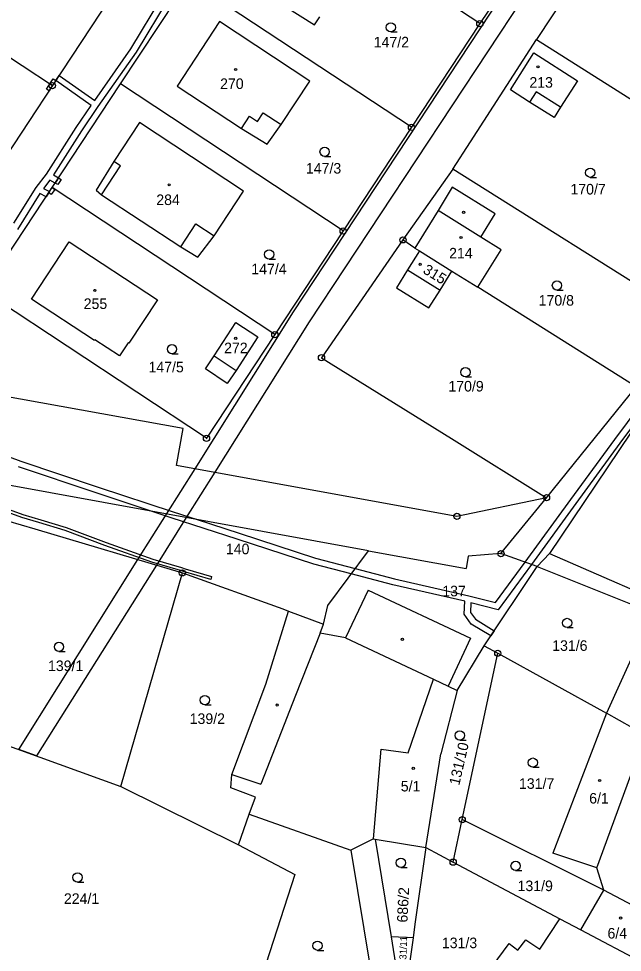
# Model space of a CAD drawing. Extents: x -747333 to -745433, y -1133152 to -1130600.
# Drawn here: x -746539.4 to -746442.1, y -1132011.9 to -1131861.6 of the extents above; entities that cross this region are included whole.
import ezdxf

# ---------------------------------------------------------------- set-up
doc = ezdxf.new("R2010")
doc.units = 0
for name, color, linetype in [('Vrstva 1', 7, 'Continuous'), ('Vrstva 18', 7, 'Continuous'), ('Vrstva 19', 7, 'Continuous'), ('Vrstva 24', 7, 'Continuous'), ('Vrstva 25', 7, 'Continuous'), ('Vrstva 3', 7, 'Continuous'), ('Vrstva 30', 7, 'Continuous'), ('Vrstva 37', 7, 'Continuous'), ('Vrstva 4', 7, 'Continuous'), ('Vrstva 6', 7, 'Continuous')]:
    doc.layers.add(name, color=color, linetype=linetype)

msp = doc.modelspace()

# ---------------------------------------------------------------- linework, layer by layer
at = {"layer": 'Vrstva 1'}
for p, q in [((-746465.11, -1131862.35), (-746501.01, -1131838.68)), ((-746454.1, -1131845.66), (-746465.11, -1131862.35)), ((-746523.03, -1131872.07), (-746512.02, -1131855.37)), ((-746476.13, -1131879.05), (-746512.02, -1131855.37)), ((-746496.38, -1131859.65), (-746491.75, -1131862.56)), ((-746491.75, -1131862.56), (-746490.9, -1131861.24)), ((-746507.05, -1131862.03), (-746513.9, -1131872.45)), ((-746492.5, -1131871.6), (-746507.05, -1131862.03)), ((-746465.11, -1131862.35), (-746476.13, -1131879.05)), ((-746534.04, -1131888.76), (-746523.03, -1131872.07)), ((-746487.14, -1131895.74), (-746523.03, -1131872.07)), ((-746513.9, -1131872.45), (-746503.53, -1131879.26)), ((-746497.13, -1131878.62), (-746492.5, -1131871.6)), ((-746519.95, -1131878.28), (-746524.08, -1131884.54)), ((-746503.2, -1131889.33), (-746519.95, -1131878.28)), ((-746503.53, -1131879.26), (-746499.39, -1131881.78)), ((-746499.39, -1131881.78), (-746497.13, -1131878.62)), ((-746476.13, -1131879.05), (-746487.14, -1131895.74)), ((-746524.08, -1131884.54), (-746526.95, -1131889.18)), ((-746545.06, -1131905.46), (-746534.04, -1131888.76)), ((-746498.15, -1131912.44), (-746534.04, -1131888.76)), ((-746526.95, -1131889.18), (-746526.08, -1131889.91)), ((-746526.08, -1131889.91), (-746513.32, -1131898.32)), ((-746507.95, -1131896.52), (-746503.2, -1131889.33)), ((-746510.54, -1131899.99), (-746507.95, -1131896.52)), ((-746487.14, -1131895.74), (-746498.15, -1131912.44)), ((-746513.32, -1131898.32), (-746510.54, -1131899.99)), ((-746474.85, -1131898.97), (-746476.75, -1131902)), ((-746475.58, -1131898.52), (-746474.85, -1131898.97)), ((-746474.85, -1131898.97), (-746469.61, -1131902.21)), ((-746476.75, -1131902), (-746478.56, -1131904.89)), ((-746471.53, -1131905.27), (-746469.61, -1131902.21)), ((-746469.61, -1131902.21), (-746465.42, -1131904.8)), ((-746509.16, -1131929.13), (-746545.06, -1131905.46)), ((-746478.56, -1131904.89), (-746473.31, -1131908.12)), ((-746473.31, -1131908.12), (-746471.53, -1131905.27)), ((-746507.95, -1131915.87), (-746504.45, -1131910.49)), ((-746504.45, -1131910.49), (-746500.88, -1131912.81)), ((-746498.15, -1131912.44), (-746509.16, -1131929.13)), ((-746500.88, -1131912.81), (-746504.4, -1131918.2)), ((-746509.31, -1131917.93), (-746507.95, -1131915.87)), ((-746505.85, -1131920.3), (-746509.31, -1131917.93)), ((-746504.4, -1131918.2), (-746505.85, -1131920.3)), ((-746512.94, -1131927.58), (-746542.46, -1131922.22)), ((-746514.01, -1131933.49), (-746512.94, -1131927.58)), ((-746483.07, -1131947.25), (-746560.7, -1131933.13)), ((-746468.81, -1131941.71), (-746514.01, -1131933.49)), ((-746454.36, -1131938.7), (-746468.81, -1131941.71)), ((-746489.62, -1131956.07), (-746483.07, -1131947.25)), ((-746483.07, -1131947.25), (-746467.34, -1131950.11)), ((-746461.71, -1131947.7), (-746466.99, -1131948.14)), ((-746466.99, -1131948.14), (-746467.34, -1131950.11))]:
    msp.add_line(p, q, dxfattribs=at)
for points in [[(-746443.47, -1131845.95), (-746455.99, -1131864.91)], [(-746521.6, -1131853.55), (-746533.99, -1131872.33)], [(-746466.63, -1131881.37), (-746455.99, -1131864.91)], [(-746455.99, -1131864.91), (-746418.01, -1131888.89)], [(-746543.81, -1131865.86), (-746533.99, -1131872.33)], [(-746460.17, -1131873.04), (-746456.41, -1131867.08)], [(-746456.41, -1131867.08), (-746449.39, -1131871.54)], [(-746533.99, -1131872.33), (-746537.79, -1131878.09)], [(-746449.39, -1131871.54), (-746452.09, -1131875.82)], [(-746457.09, -1131875.01), (-746460.17, -1131873.04)], [(-746453.14, -1131877.48), (-746457.09, -1131875.01)], [(-746452.09, -1131875.82), (-746453.14, -1131877.48)], [(-746537.79, -1131878.09), (-746546.37, -1131891.11)], [(-746469.48, -1131885.78), (-746466.63, -1131881.37)], [(-746469.48, -1131885.78), (-746477.5, -1131897.18)], [(-746431.68, -1131909.51), (-746469.48, -1131885.78)], [(-746469.56, -1131888.71), (-746471.81, -1131892.44)], [(-746462.62, -1131892.99), (-746469.56, -1131888.71)], [(-746471.81, -1131892.44), (-746475.58, -1131898.52)], [(-746464.95, -1131896.72), (-746462.62, -1131892.99)], [(-746537.36, -1131906.73), (-746531.27, -1131897.47), (-746517.04, -1131906.83), (-746521.67, -1131913.82), (-746521.78, -1131913.76), (-746523.18, -1131915.87), (-746527.14, -1131913.27), (-746527.21, -1131913.37), (-746537.36, -1131906.73)], [(-746477.5, -1131897.18), (-746490.63, -1131916.16)], [(-746475.58, -1131898.52), (-746477.5, -1131897.18)], [(-746461.69, -1131898.76), (-746464.95, -1131896.72)], [(-746465.42, -1131904.8), (-746461.69, -1131898.76)], [(-746439.92, -1131920.87), (-746465.42, -1131904.8)], [(-746490.63, -1131916.16), (-746469.66, -1131929.19)], [(-746454.36, -1131938.7), (-746439.92, -1131920.87)], [(-746438.95, -1131925.52), (-746453.89, -1131947.67)], [(-746469.66, -1131929.19), (-746454.36, -1131938.7)], [(-746461.71, -1131947.7), (-746454.36, -1131938.7)], [(-746543.47, -1131941.76), (-746536.83, -1131943.73)], [(-746536.83, -1131943.73), (-746513.04, -1131950.81)], [(-746455.89, -1131949.78), (-746461.71, -1131947.7)], [(-746455.89, -1131949.78), (-746453.89, -1131947.67)], [(-746453.89, -1131947.67), (-746430.93, -1131957.68)], [(-746464.41, -1131962.54), (-746455.89, -1131949.78)], [(-746455.89, -1131949.78), (-746437.32, -1131957.2)], [(-746522.94, -1131985.19), (-746513.04, -1131950.81)], [(-746513.04, -1131950.81), (-746496.86, -1131956.6)], [(-746483.11, -1131953.58), (-746486.74, -1131961.29)], [(-746483.11, -1131953.58), (-746466.6, -1131961.34)], [(-746496.86, -1131956.6), (-746495.93, -1131956.95)], [(-746499.59, -1131968.72), (-746495.93, -1131956.95)], [(-746495.93, -1131956.95), (-746490.28, -1131959.09)], [(-746437.32, -1131957.2), (-746444.69, -1131973.38)], [(-746490.84, -1131960.52), (-746490.28, -1131959.09)], [(-746486.74, -1131961.29), (-746490.84, -1131960.52)], [(-746466.6, -1131961.34), (-746470.23, -1131969.05)], [(-746468.74, -1131969.75), (-746464.41, -1131962.54)], [(-746464.41, -1131962.54), (-746462.22, -1131963.75)], [(-746467.95, -1131990.55), (-746462.22, -1131963.75)], [(-746462.22, -1131963.75), (-746444.69, -1131973.38)], [(-746505.1, -1131983.28), (-746499.59, -1131968.72)], [(-746468.74, -1131969.75), (-746471.42, -1131979.96)], [(-746470.23, -1131969.05), (-746468.74, -1131969.75)], [(-746552.82, -1131974.44), (-746522.94, -1131985.19)], [(-746444.69, -1131973.38), (-746453.36, -1131995.97)], [(-746438.41, -1131976.96), (-746444.69, -1131973.38)], [(-746473.83, -1131995.06), (-746471.42, -1131979.96)], [(-746505.25, -1131985.42), (-746505.1, -1131983.28)], [(-746522.94, -1131985.19), (-746504, -1131994.6)], [(-746501.26, -1131986.91), (-746505.25, -1131985.42)], [(-746502.27, -1131989.69), (-746501.26, -1131986.91)], [(-746504, -1131994.6), (-746502.27, -1131989.69)], [(-746502.27, -1131989.69), (-746485.89, -1131995.45)], [(-746469.41, -1131997.4), (-746467.95, -1131990.55)], [(-746445.14, -1132001.9), (-746467.95, -1131990.55)], [(-746482.26, -1131993.62), (-746485.89, -1131995.45)], [(-746482.26, -1131993.62), (-746481.99, -1131993.67)], [(-746481.99, -1131993.67), (-746473.83, -1131995.06)], [(-746481.99, -1131993.67), (-746479.42, -1132009.41)], [(-746504, -1131994.6), (-746494.93, -1131999.39)], [(-746485.89, -1131995.45), (-746480.65, -1132027.32)], [(-746473.83, -1131995.06), (-746475.57, -1132007.36)], [(-746473.83, -1131995.06), (-746469.41, -1131997.4)], [(-746446.26, -1131998.3), (-746453.36, -1131995.97)], [(-746469.41, -1131997.4), (-746452.2, -1132006.5)], [(-746445.14, -1132001.9), (-746446.26, -1131998.3)], [(-746494.93, -1131999.39), (-746499.57, -1132013.64)], [(-746448.81, -1132008.32), (-746445.14, -1132001.9)], [(-746434.75, -1132007.36), (-746445.14, -1132001.9)], [(-746475.57, -1132007.36), (-746475.88, -1132009.57)], [(-746455.47, -1132011.39), (-746452.2, -1132006.5)], [(-746452.2, -1132006.5), (-746448.81, -1132008.32)], [(-746448.81, -1132008.32), (-746438.69, -1132013.68)], [(-746479.42, -1132009.41), (-746477.54, -1132021.27)], [(-746475.88, -1132009.57), (-746479.42, -1132009.41)], [(-746475.88, -1132009.57), (-746477.54, -1132021.27)], [(-746463.13, -1132014.2), (-746460.4, -1132010.51)], [(-746460.4, -1132010.51), (-746459.01, -1132011.55)], [(-746459.01, -1132011.55), (-746457.7, -1132009.89)], [(-746457.7, -1132009.89), (-746455.47, -1132011.39)]]:
    msp.add_lwpolyline(points, dxfattribs=at)
at = {"layer": 'Vrstva 24'}
for p, q in [((-746465.145355, -1131862.314645), (-746465.074645, -1131862.385355)), ((-746534.04, -1131872.33), (-746533.94, -1131872.33)), ((-746476.165355, -1131879.014645), (-746476.094645, -1131879.085355)), ((-746487.175355, -1131895.704645), (-746487.104645, -1131895.775355)), ((-746477.55, -1131897.18), (-746477.45, -1131897.18)), ((-746498.185355, -1131912.404645), (-746498.114645, -1131912.475355)), ((-746490.68, -1131916.16), (-746490.58, -1131916.16)), ((-746509.195355, -1131929.094645), (-746509.124645, -1131929.165355)), ((-746454.41, -1131938.7), (-746454.31, -1131938.7)), ((-746468.845355, -1131941.674645), (-746468.774645, -1131941.745355)), ((-746461.76, -1131947.7), (-746461.66, -1131947.7)), ((-746513.09, -1131950.81), (-746512.99, -1131950.81)), ((-746462.27, -1131963.75), (-746462.17, -1131963.75)), ((-746468, -1131990.55), (-746467.9, -1131990.55)), ((-746469.46, -1131997.4), (-746469.36, -1131997.4))]:
    msp.add_line(p, q, dxfattribs=at)
for centre in [(-746465.11, -1131862.35), (-746533.99, -1131872.33), (-746476.13, -1131879.05), (-746487.14, -1131895.74), (-746477.5, -1131897.18), (-746498.15, -1131912.44), (-746490.63, -1131916.16), (-746509.16, -1131929.13), (-746454.36, -1131938.7), (-746468.81, -1131941.71), (-746461.71, -1131947.7), (-746513.04, -1131950.81), (-746462.22, -1131963.75), (-746467.95, -1131990.55), (-746469.41, -1131997.4)]:
    msp.add_circle(centre, 0.499289, dxfattribs=at)
at = {"layer": 'Vrstva 25'}
for p, q in [((-746479.46, -1131863.7), (-746478.46, -1131863.7)), ((-746490.12, -1131883.74), (-746489.12, -1131883.74)), ((-746447.32, -1131887.11), (-746446.32, -1131887.11)), ((-746499.06, -1131900.27), (-746498.06, -1131900.27)), ((-746452.68, -1131905.27), (-746451.68, -1131905.27)), ((-746514.72, -1131915.53), (-746513.72, -1131915.53)), ((-746467.43, -1131919.24), (-746466.43, -1131919.24)), ((-746451.05, -1131959.63), (-746450.05, -1131959.63)), ((-746532.93, -1131963.47), (-746531.93, -1131963.47)), ((-746509.43, -1131972.05), (-746508.43, -1131972.05)), ((-746468.34, -1131977.73), (-746467.34, -1131977.73)), ((-746456.57, -1131982.12), (-746455.57, -1131982.12)), ((-746477.83, -1131998.25), (-746476.83, -1131998.25)), ((-746459.34, -1131998.75), (-746458.34, -1131998.75)), ((-746529.94, -1132000.6), (-746528.94, -1132000.6)), ((-746491.27, -1132011.6), (-746490.27, -1132011.6))]:
    msp.add_line(p, q, dxfattribs=at)
for centre, radius in [((-746479.46, -1131862.95), 0.75), ((-746455.75, -1131869.32), 0.174503), ((-746504.46, -1131869.73), 0.174503), ((-746490.12, -1131882.99), 0.75), ((-746447.32, -1131886.36), 0.75), ((-746515.18, -1131888.32), 0.174503), ((-746467.72, -1131892.75), 0.174503), ((-746468.14, -1131896.79), 0.174503), ((-746499.06, -1131899.52), 0.75), ((-746474.72, -1131901.13), 0.174503), ((-746452.68, -1131904.52), 0.75), ((-746527.15, -1131905.32), 0.174503), ((-746504.45, -1131913.04), 0.174503), ((-746514.72, -1131914.78), 0.75), ((-746467.43, -1131918.49), 0.75), ((-746451.05, -1131958.88), 0.75), ((-746532.93, -1131962.72), 0.75), ((-746477.59, -1131961.51), 0.174503), ((-746509.43, -1131971.3), 0.75), ((-746497.77, -1131972.09), 0.174503), ((-746468.34, -1131976.98), 0.75), ((-746456.57, -1131981.37), 0.75), ((-746475.84, -1131982.28), 0.174503), ((-746445.81, -1131984.24), 0.174503), ((-746477.83, -1131997.5), 0.75), ((-746459.34, -1131998), 0.75), ((-746529.94, -1131999.85), 0.75), ((-746442.42, -1132006.4), 0.174503), ((-746491.27, -1132010.85), 0.75)]:
    msp.add_circle(centre, radius, dxfattribs=at)
at = {"layer": 'Vrstva 3'}
for points in [[(-746507.05, -1131862.03), (-746513.9, -1131872.45)], [(-746492.5, -1131871.6), (-746507.05, -1131862.03)], [(-746460.17, -1131873.04), (-746456.41, -1131867.08)], [(-746456.41, -1131867.08), (-746449.39, -1131871.54)], [(-746513.9, -1131872.45), (-746503.53, -1131879.26)], [(-746497.13, -1131878.62), (-746492.5, -1131871.6)], [(-746449.39, -1131871.54), (-746452.09, -1131875.82)], [(-746457.09, -1131875.01), (-746460.17, -1131873.04)], [(-746456.02, -1131873.33), (-746457.09, -1131875.01)], [(-746452.09, -1131875.82), (-746456.02, -1131873.33)], [(-746500.92, -1131878.11), (-746500.02, -1131876.73)], [(-746500.02, -1131876.73), (-746497.13, -1131878.62)], [(-746519.95, -1131878.28), (-746524.08, -1131884.54)], [(-746503.2, -1131889.33), (-746519.95, -1131878.28)], [(-746503.53, -1131879.26), (-746502.24, -1131877.27)], [(-746502.24, -1131877.27), (-746500.92, -1131878.11)], [(-746523.02, -1131885.25), (-746524.08, -1131884.54)], [(-746526.08, -1131889.91), (-746523.02, -1131885.25)], [(-746526.08, -1131889.91), (-746513.32, -1131898.32)], [(-746507.95, -1131896.52), (-746503.2, -1131889.33)], [(-746471.81, -1131892.44), (-746475.58, -1131898.52)], [(-746464.95, -1131896.72), (-746471.81, -1131892.44)], [(-746513.32, -1131898.32), (-746510.87, -1131894.59)], [(-746510.87, -1131894.59), (-746507.95, -1131896.52)], [(-746537.36, -1131906.73), (-746531.27, -1131897.47), (-746517.04, -1131906.83), (-746521.67, -1131913.82), (-746521.78, -1131913.76), (-746523.18, -1131915.87), (-746527.14, -1131913.27), (-746527.21, -1131913.37), (-746537.36, -1131906.73)], [(-746461.69, -1131898.76), (-746464.95, -1131896.72)], [(-746474.85, -1131898.97), (-746476.75, -1131902)], [(-746475.58, -1131898.52), (-746474.85, -1131898.97)], [(-746474.85, -1131898.97), (-746469.61, -1131902.21)], [(-746474.85, -1131898.97), (-746469.61, -1131902.21)], [(-746465.42, -1131904.8), (-746461.69, -1131898.76)], [(-746476.75, -1131902), (-746471.53, -1131905.27)], [(-746471.53, -1131905.27), (-746469.61, -1131902.21)], [(-746469.61, -1131902.21), (-746465.42, -1131904.8)], [(-746507.95, -1131915.87), (-746504.45, -1131910.49)], [(-746504.45, -1131910.49), (-746500.88, -1131912.81)], [(-746500.88, -1131912.81), (-746504.4, -1131918.2)], [(-746507.95, -1131915.87), (-746504.4, -1131918.2)], [(-746476.68, -1131979.81), (-746472.6, -1131967.94)], [(-746472.6, -1131967.94), (-746470.23, -1131969.05)], [(-746468.74, -1131969.75), (-746471.42, -1131979.96)], [(-746470.23, -1131969.05), (-746468.74, -1131969.75)], [(-746444.69, -1131973.38), (-746453.36, -1131995.97)], [(-746438.41, -1131976.96), (-746444.69, -1131973.38)], [(-746446.26, -1131998.3), (-746438.41, -1131976.96)], [(-746482.26, -1131993.62), (-746481, -1131979.2)], [(-746481, -1131979.2), (-746476.68, -1131979.81)], [(-746473.83, -1131995.06), (-746471.42, -1131979.96)], [(-746482.26, -1131993.62), (-746481.99, -1131993.67)], [(-746481.99, -1131993.67), (-746473.83, -1131995.06)], [(-746446.26, -1131998.3), (-746453.36, -1131995.97)], [(-746448.81, -1132008.32), (-746445.14, -1132001.9)], [(-746434.75, -1132007.36), (-746445.14, -1132001.9)], [(-746448.81, -1132008.32), (-746438.69, -1132013.68)]]:
    msp.add_lwpolyline(points, dxfattribs=at)
at = {"layer": 'Vrstva 30'}
for p, q in [((-746495.13, -1131908.77), (-746448.92, -1131838.75)), ((-746446.4, -1131840.37), (-746492.61, -1131910.39)), ((-746521.34, -1131866.39), (-746514.62, -1131855.22)), ((-746514.03, -1131856.17), (-746520.5, -1131866.93)), ((-746527.18, -1131874.74), (-746521.34, -1131866.39)), ((-746520.5, -1131866.93), (-746526.65, -1131875.72)), ((-746532.91, -1131870.69), (-746527.18, -1131874.74)), ((-746534.96, -1131872.89), (-746534.41, -1131872.05)), ((-746534.41, -1131872.05), (-746533.86, -1131871.22)), ((-746533.99, -1131872.33), (-746534.41, -1131872.05)), ((-746533.44, -1131871.5), (-746533.99, -1131872.33)), ((-746533.86, -1131871.22), (-746533.44, -1131871.5)), ((-746527.75, -1131875.56), (-746533.46, -1131871.53)), ((-746534.54, -1131873.16), (-746534.96, -1131872.89)), ((-746530.16, -1131879.07), (-746527.75, -1131875.56)), ((-746526.65, -1131875.72), (-746529.32, -1131879.63)), ((-746534.94, -1131886.61), (-746530.16, -1131879.07)), ((-746529.32, -1131879.63), (-746533.83, -1131886.72)), ((-746536.61, -1131888.75), (-746534.94, -1131886.61)), ((-746534.4, -1131887.55), (-746535.44, -1131888.88)), ((-746533.56, -1131888.03), (-746534.4, -1131887.55)), ((-746533.83, -1131886.72), (-746533, -1131887.19)), ((-746532.57, -1131887.43), (-746533.12, -1131888.27)), ((-746533, -1131887.19), (-746532.57, -1131887.43)), ((-746540.19, -1131894.51), (-746536.61, -1131888.75)), ((-746535.44, -1131888.88), (-746534.46, -1131889.4)), ((-746534.59, -1131889.59), (-746534.19, -1131888.98)), ((-746533.62, -1131889.04), (-746534.17, -1131889.87)), ((-746533.12, -1131888.27), (-746533.56, -1131888.03)), ((-746536.02, -1131889.7), (-746539.63, -1131895.5)), ((-746535.01, -1131890.23), (-746536.02, -1131889.7)), ((-746534.17, -1131889.87), (-746534.59, -1131889.59)), ((-746511.01, -1131934.04), (-746495.13, -1131908.77)), ((-746492.61, -1131910.39), (-746507.83, -1131934.61)), ((-746515.59, -1131941.33), (-746511.01, -1131934.04)), ((-746507.83, -1131934.61), (-746512.41, -1131941.91)), ((-746520.21, -1131948.68), (-746515.59, -1131941.33)), ((-746512.41, -1131941.91), (-746517.22, -1131949.57)), ((-746539.42, -1131979.26), (-746520.21, -1131948.68)), ((-746517.22, -1131949.57), (-746536.53, -1131980.3)), ((-746536.53, -1131980.3), (-746539.42, -1131979.26))]:
    msp.add_line(p, q, dxfattribs=at)
for points in [[(-746533.46, -1131871.53), (-746532.91, -1131870.69)], [(-746533.99, -1131872.33), (-746534.54, -1131873.16)], [(-746534.41, -1131872.05), (-746533.99, -1131872.33)], [(-746533.56, -1131888.03), (-746533, -1131887.19)], [(-746533, -1131887.19), (-746533.56, -1131888.03)], [(-746534.19, -1131888.98), (-746534.04, -1131888.76), (-746533.62, -1131889.04)], [(-746534.46, -1131889.4), (-746535.01, -1131890.23)], [(-746443.35, -1131929.34), (-746437.38, -1131921.32)], [(-746436.58, -1131921.92), (-746442.55, -1131929.94)], [(-746450.43, -1131939.01), (-746443.35, -1131929.34)], [(-746545.8, -1131930.35), (-746539.1, -1131932.8)], [(-746442.55, -1131929.94), (-746449.63, -1131939.61)], [(-746526.93, -1131937.92), (-746539.44, -1131933.74)], [(-746539.1, -1131932.8), (-746526.61, -1131936.98)], [(-746538.91, -1131941.89), (-746544.74, -1131939.78), (-746549.15, -1131938.47), (-746552.27, -1131938.03), (-746552.58, -1131938.35), (-746553.1, -1131938.15), (-746552.74, -1131937.79), (-746553.59, -1131937.12)], [(-746526.61, -1131936.98), (-746514.54, -1131940.97)], [(-746517.89, -1131940.92), (-746526.93, -1131937.92)], [(-746544.58, -1131939.3), (-746538.75, -1131941.41), (-746535.87, -1131942.28)], [(-746457.79, -1131949.1), (-746450.43, -1131939.01)], [(-746449.63, -1131939.61), (-746456.8, -1131949.45)], [(-746514.84, -1131941.93), (-746517.89, -1131940.92)], [(-746514.54, -1131940.97), (-746510.64, -1131942.24)], [(-746517.95, -1131949.09), (-746525.53, -1131946.39), (-746531.96, -1131943.99), (-746536.16, -1131942.72), (-746538.91, -1131941.89)], [(-746535.87, -1131942.28), (-746531.8, -1131943.51), (-746525.35, -1131945.93), (-746517.79, -1131948.61)], [(-746504.22, -1131945.36), (-746514.84, -1131941.93)], [(-746510.64, -1131942.24), (-746503.91, -1131944.41)], [(-746503.91, -1131944.41), (-746491.57, -1131948.43)], [(-746491.85, -1131949.39), (-746504.22, -1131945.36)], [(-746517.79, -1131948.61), (-746513.19, -1131949.97), (-746512.61, -1131950.14), (-746508.33, -1131951.38), (-746508.47, -1131951.86), (-746512.89, -1131950.58), (-746513.33, -1131950.45), (-746517.95, -1131949.09)], [(-746491.57, -1131948.43), (-746485.19, -1131950.11)], [(-746462.58, -1131955.6), (-746457.79, -1131949.1)], [(-746485.83, -1131950.97), (-746491.85, -1131949.39)], [(-746485.19, -1131950.11), (-746478.88, -1131951.76)], [(-746456.8, -1131949.45), (-746462.18, -1131956.74)], [(-746479.12, -1131952.74), (-746485.83, -1131950.97)], [(-746478.88, -1131951.76), (-746466.89, -1131954.49)], [(-746467.53, -1131955.36), (-746479.12, -1131952.74)], [(-746466.89, -1131954.49), (-746462.58, -1131955.6)], [(-746467.66, -1131957.46), (-746467.53, -1131955.36)], [(-746466.55, -1131955.61), (-746466.64, -1131957.17)], [(-746462.18, -1131956.74), (-746466.55, -1131955.61)], [(-746466.51, -1131959.05), (-746467.66, -1131957.46)], [(-746466.64, -1131957.17), (-746465.83, -1131958.29)], [(-746463.35, -1131960.96), (-746466.51, -1131959.05)], [(-746465.83, -1131958.29), (-746462.8, -1131960.13)], [(-746462.8, -1131960.13), (-746463.35, -1131960.96)]]:
    msp.add_lwpolyline(points, dxfattribs=at)
at = {"layer": 'Vrstva 37'}
for centre in [(-746455.75, -1131869.32), (-746504.46, -1131869.73), (-746515.18, -1131888.32), (-746468.14, -1131896.79), (-746474.72, -1131901.13), (-746527.15, -1131905.32), (-746504.45, -1131913.04), (-746475.84, -1131982.28), (-746445.81, -1131984.24), (-746442.42, -1132006.4)]:
    msp.add_circle(centre, 0.174503, dxfattribs=at)
at = {"layer": 'Vrstva 4'}
for p, q in [((-746500.92, -1131878.11), (-746500.02, -1131876.73)), ((-746500.02, -1131876.73), (-746497.13, -1131878.62)), ((-746503.53, -1131879.26), (-746502.24, -1131877.27)), ((-746502.24, -1131877.27), (-746500.92, -1131878.11)), ((-746523.02, -1131885.25), (-746524.08, -1131884.54)), ((-746526.08, -1131889.91), (-746523.02, -1131885.25)), ((-746513.32, -1131898.32), (-746510.87, -1131894.59)), ((-746510.87, -1131894.59), (-746507.95, -1131896.52)), ((-746476.75, -1131902), (-746471.53, -1131905.27)), ((-746507.95, -1131915.87), (-746504.4, -1131918.2))]:
    msp.add_line(p, q, dxfattribs=at)
for points in [[(-746456.02, -1131873.33), (-746457.09, -1131875.01)], [(-746452.09, -1131875.82), (-746456.02, -1131873.33)], [(-746464.95, -1131896.72), (-746471.81, -1131892.44)], [(-746490.84, -1131960.52), (-746494.8, -1131970.55)], [(-746486.74, -1131961.29), (-746472.6, -1131967.94)], [(-746476.68, -1131979.81), (-746472.6, -1131967.94)], [(-746472.6, -1131967.94), (-746470.23, -1131969.05)], [(-746494.8, -1131970.55), (-746500.43, -1131984.82)], [(-746446.26, -1131998.3), (-746438.41, -1131976.96)], [(-746482.26, -1131993.62), (-746481, -1131979.2)], [(-746481, -1131979.2), (-746476.68, -1131979.81)], [(-746505.1, -1131983.28), (-746500.43, -1131984.82)]]:
    msp.add_lwpolyline(points, dxfattribs=at)
at = {"layer": 'Vrstva 6'}
msp.add_lwpolyline([(-746490.28, -1131959.09), (-746489.62, -1131956.07)], dxfattribs=at)

# ---------------------------------------------------------------- texts
at = {"layer": 'Vrstva 18'}
for s, p in [('147/2', (-746482.210095, -1131866.18)), ('147/3', (-746493.140095, -1131886.5)), ('170/7', (-746450.51, -1131889.87)), ('147/4', (-746501.940095, -1131902.72)), ('170/8', (-746455.63, -1131907.77)), ('147/5', (-746518.510095, -1131918.51)), ('170/9', (-746470.18, -1131921.6)), ('140', (-746506.033812, -1131947.8)), ('137', (-746471.15881, -1131954.59)), ('131/6', (-746453.45, -1131963.37)), ('139/1', (-746534.7, -1131966.62)), ('139/2', (-746511.87, -1131975.14)), ('131/7', (-746458.8, -1131985.59)), ('131/9', (-746459.03, -1132002.06)), ('224/1', (-746532.14, -1132004.12)), ('131/3', (-746471.23, -1132011.25))]:
    msp.add_text(s, height=1.7, dxfattribs=at).set_placement(p)
for s, height, rotation, p in [('131/10', 1.7, 77.03073, (-746468.43, -1131985.12)), ('686/2', 1.7, 87.15051, (-746476.78, -1132007.16)), ('131/11', 1.14, 87.89832, (-746476.98, -1132013.97))]:
    msp.add_text(s, height=height, rotation=rotation, dxfattribs=at).set_placement(p)
at = {"layer": 'Vrstva 19'}
for s, p in [('213', (-746457.13, -1131872.67)), ('270', (-746506.966548, -1131872.88)), ('284', (-746517.251545, -1131891.57)), ('214', (-746470.06, -1131900.17)), ('255', (-746528.951545, -1131908.31)), ('272', (-746506.321545, -1131915.43)), ('5/1', (-746477.85, -1131986.01)), ('6/1', (-746447.49, -1131987.96)), ('6/4', (-746444.54, -1132009.7))]:
    msp.add_text(s, height=1.7, dxfattribs=at).set_placement(p)
msp.add_text('315', height=1.7, rotation=328.54797, dxfattribs=at).set_placement((-746474.418601, -1131902.427944))

doc.saveas('drawing.dxf')
